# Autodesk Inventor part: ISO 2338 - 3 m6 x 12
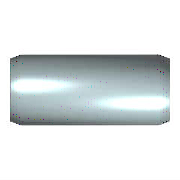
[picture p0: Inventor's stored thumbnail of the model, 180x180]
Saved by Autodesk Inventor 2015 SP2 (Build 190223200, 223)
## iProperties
Created: 2014-02
Part Number: ISO 2338 - 3 m6 x 12
Material: Edelstahl, austenitisch
Description: Zylinderstift
Document SubType Name: Modeling
Standard: ISO 2338
Designer: rYan
Standards Organization: DIN
Language: de-DE
Size Designation: 3 m6 x 12
Categories: <MemberInstance><Categories><Category DisplayName="Verbindungselemente" InternalName="e4da775c-781d-43d5-af7c-5136215cf5a6" Mnemonic="FSTN"><Category DisplayNam
Density: 8 g/cm^3
Appearance: Halbpoliert
IsCustomPart: 0
Author: rYan
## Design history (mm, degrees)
sketch "Skizze"
  geometry: C1 r 1.5 at (0, 0); 1 further point
  constraints: 1 centre point, 1 coincident
  dimensions: "d1" = 3 diameter of C1 (= NND)
extrude "Körper" new body sketch "Skizze" distance "d2" = 12 (= NLG); taper "d3" = 0 deg
body "Solid1"
chamfer "Fase1" distance "d4" = 0.5 (= PHH); stored, may be unused: angle "d5" = 15 deg (= FAWI), second distance "d11" = 0.5 (= PHH)
chamfer "Fase2" distance "d8" = 0.5 (= PHH); stored, may be unused: angle "d9" = 15 deg (= FAWI), second distance "d12" = 0.5 (= PHH)
other parameters: "NND" = 3 [user parameter; used in 1 equation term], "NLG" = 12 [user parameter; used in 1 equation term], "PHH" = 0.5 [user parameter; used in 4 equation terms], "FAWI" = 15 deg [user parameter; used in 2 equation terms], "d13" = 0, "d15" = 0, "d16" = 0, "KAH" = 0 [user parameter]
